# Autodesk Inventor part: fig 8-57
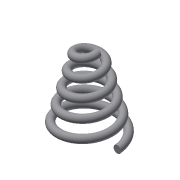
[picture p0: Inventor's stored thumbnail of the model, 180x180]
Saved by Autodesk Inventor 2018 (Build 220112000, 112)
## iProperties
Shininess: 77.0
Length Units: 11269
Angle Units: 11279
Time Units: 11290
Mass Units: 11283
Length Display Precision: 3
Angle Display Precision: 2
Created: 2002-01
Part Number: fig 8-57
Document SubType Name: Modeling
Designer: CADSoft
Density: 1 g/cm^3
Material: Generic
Appearance: Default
Density: 0.0
Volumn: 0.0
Area: 0.0
PropertySet Name: Model Information
Control State: 0
Master: False
Checked Out: False
Author: CADSoft
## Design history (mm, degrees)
sketch "Sketch2"
  geometry: C1 r 2.5 at (-19.895, -0.092)
  constraints: 1 centre point
  dimensions: "d0" = 5 diameter of C1
coil "Coil5" sketch "Sketch2" pitch "d35" = 10; turns "d37" = 5; dims "d36" = 10, "d38" = -15 deg, angle "d39" = 90 deg, angle "d40" = 90 deg, "d41" = 0, "d42" = 0
body "Solid1"
